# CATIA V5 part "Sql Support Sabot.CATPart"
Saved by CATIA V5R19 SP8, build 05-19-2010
Part number: Sql Support Sabot
Publications: "Plan.1", "Plan.3", "Droite.1", "Point.3", "Plan.5"
Bounding box of the stored display mesh (mm): x 0 to 0, y 0 to 0, z -1500 to -830
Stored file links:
  G:\EU_thinkMotion\CFAO_2010\MMS_groupe3\MMS_groupe3\rdalborgo\rdalborgo\Sql Support Sabot.CATPart
  G:\EU_thinkMotion\CFAO_2010\MMS_groupe3\MMS_groupe3\rdalborgo\rdalborgo\rdalborgo.CATProduct
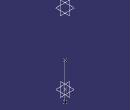
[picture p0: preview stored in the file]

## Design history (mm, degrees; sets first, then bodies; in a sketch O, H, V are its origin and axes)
Set1
  Plane1: linked copy from another document
  Point1 "Axe sabot": linked copy from another document
  Plane2: linked copy from another document
  Point2 "B verin frein": linked copy from another document
  Plane3: linked copy from another document
Set2
  Plane4: type OffsetPt, RefPlane Plane1, RefPoint Point1
  Plane5: type OffsetPt, RefPlane Plane2, RefPoint Point1
  Line1: type PtPt, FirstPoint Point3, SecondPoint Point2
  Point3: (0, 0, 470), relative to Point1
  Plane6: type OffsetPt, RefPlane Plane3, RefPoint Point1
Body1 (main body)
